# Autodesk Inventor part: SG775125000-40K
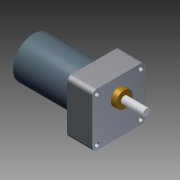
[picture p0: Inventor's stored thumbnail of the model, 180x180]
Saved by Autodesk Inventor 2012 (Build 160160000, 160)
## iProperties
Created: 2014-02
Part Number: SG775125000-40K
Material: Default
Document SubType Name: Modeling
Designer: Aser
Density: 1 g/cm^3
Author: Aser
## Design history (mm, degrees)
sketch "Sketch1"
  geometry: L1 (0, 0)-(60, 0); L2 (60, 0)-(60, -60); L3 (60, -60)-(0, -60); L4 (0, -60)-(0, 0); L5 (54.75, -54.75)-(54.75, -5.25); L6 (54.75, -5.25)-(5.25, -5.25); L7 (5.25, -5.25)-(5.25, -54.75); L8 (5.25, -54.75)-(54.75, -54.75); L9 (30, -5.25)-(30, -54.75); C1 r 2.5 at (54.75, -5.25); C2 r 2.5 at (54.75, -54.75); C3 r 2.5 at (5.25, -54.75); C4 r 2.5 at (5.25, -5.25); C5 r 9.25 at (40, -30)
  constraints: 18 end point, 5 centre point, 4 coincident, 4 parallel, 2 midpoint, 2 perpendicular, 1 horizontal, 3 other
  dimensions: "d0" = 60 distance of L2.end L3.end; "d1" = 60 distance of L1.end L2.end; "d2" = 49.5 distance of L5.start L5.end; "d3" = 49.5 distance of L7.end L5.start (derived); "d4" = 5 diameter of C1; "d5" = 5 diameter of C2; "d6" = 5 diameter of C3; "d7" = 5 diameter of C4; "d8" = 18.5 diameter of C5; "d9" = 10 distance from line of L9 C5.centre; "d10" = 24.75 distance from line of L8 C5.centre
extrude "Extrusion1" new body sketch "Sketch1" distance "d11" = 28.5; taper "d12" = 0 deg
sketch "Sketch2"
  geometry: C1 r 9.25 at (30, 40) reference
extrude "Extrusion2" join sketch "Sketch2" distance "d13" = 6; taper "d14" = 0 deg
fillet "Fillet1" dims "d15" = 5
sketch "Sketch3"
  geometry: C1 r 9.25 at (0, 0) reference; C2 r 4 at (0, 0); 1 further point
  constraints: 1 centre point, 1 coincident
  dimensions: "d16" = 8 diameter of C2
extrude "Extrusion3" join sketch "Sketch3" distance "d17" = 25; taper "d18" = 0 deg
sketch "Sketch4"
  geometry: L1 (-5, 60)-(-55, 60) reference; L2 (-60, 55)-(-60, 5) reference; C1 r 23 at (-30, 30); 1 further point
  constraints: 1 centre point
  dimensions: "d19" = 46 diameter of C1; "d20" = 30 distance from line of L1 C1.centre; "d21" = 30 distance from line of C1.centre L2
extrude "Extrusion4" join sketch "Sketch4" distance "d22" = 68; taper "d23" = 0 deg
body "Solid1"
